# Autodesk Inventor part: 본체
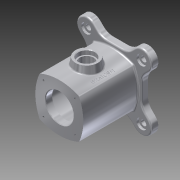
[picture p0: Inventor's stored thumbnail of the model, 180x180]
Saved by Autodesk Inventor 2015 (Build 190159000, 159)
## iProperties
Created: 2016-05
Part Number: 본체
Material: 알루미늄 6061
Document SubType Name: Modeling
Designer: Administrator
Density: 2.7 g/cm^3
Appearance: 알루미늄 - 평지
Mass: 1104.93 g
Surface Area: 865.283 cm^2
Volume: 409.235 cm^3
Author: Administrator
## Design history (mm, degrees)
sketch "스케치1" dims "d0" = 70
  geometry: L1 (49, 49)-(-49, 49); L2 (-49, 49)-(-49, -49); L3 (-49, -49)-(49, -49); L4 (49, -49)-(49, 49); L5 (49, 49)-(-49, -49); L6 (-49, 49)-(49, -49); L7 (0, -70)-(0, 70); L8 (-70, 0)-(70, 0); L9 (0, 0)-(-60.519, 60.519); L10 (0, 0)-(85.587, 0); L11 (-49, 23.544)-(-62.225, 36.77); L12 (-23.544, 49)-(-36.77, 62.225); L13 (-49, -23.544)-(-62.225, -36.77); L14 (-23.544, -49)-(-36.77, -62.225); L15 (49, 23.544)-(62.225, 36.77); L16 (23.544, 49)-(36.77, 62.225); L17 (23.544, -49)-(36.77, -62.225); L18 (49, -23.544)-(62.225, -36.77); L19 (23.544, 49)-(49, 49); L20 (49, 49)-(49, 23.544); L21 (49, -23.544)-(49, -49); L22 (23.544, -49)-(49, -49); L23 (-49, -23.544)-(-49, -49); L24 (-49, -49)-(-23.544, -49); A1 r 18 centre (-49.497, 49.497) between (-35.239, 60.483) and (-60.483, 35.239); A2 r 18 centre (-49.497, -49.497) between (-60.483, -35.239) and (-35.239, -60.483); A3 r 18 centre (49.497, 49.497) between (60.483, 35.239) and (35.239, 60.483); A4 r 18 centre (49.497, -49.497) between (35.239, -60.483) and (60.483, -35.239); 1 further point
  constraints: 48 end point, 21 symmetric about line, 16 point on circle, 5 collinear, 5 point on line, 4 centre point, 4 midpoint, 3 horizontal, 2 parallel, 1 coincident, 1 equal length, 1 perpendicular, 1 vertical, 12 other
  dimensions: "d1" = 98 distance of L3.end L2.end; "d2" = 98 distance of L2.end L1.end; "d4" = 135 deg angle of L10 L9; "d5" = 18 radius of A1; "d6" = 36 diameter of L11 L9; "d7" = 36 diameter of L12 L9
extrude "돌출1" new body sketch "스케치1" distance "d8" = 12; taper "d9" = 0 deg
fillet "모깎기1" dims "d10" = 25
sketch "스케치2"
  geometry: A1 r 18 centre (49.497, -49.497) between (36.77, -62.225) and (62.225, -36.77) reference; 2 further points
  constraints: 1 coincident
hole "구멍1" sketch "스케치2" at (49.497, -49.497) diameter "d11" = 10; stored, may be unused: countersink angle "d15" = 90 deg, drill point angle "d17" = 118 deg; dims "d12" = 6, "d13" = 18, "d14" = 4, "d16" = 15
sketch "스케치3"
  geometry: L1 (35.355, 35.355)-(-35.355, -35.355); L2 (0, 0)-(50, 0); L3 (35.355, -35.355)-(-35.355, 35.355); L4 (0, 0)-(50, 0); L5 (0, -43)-(0, 43); L6 (-43, 0)-(43, 0); C1 r 43 at (0, 0); A1 r 50 centre (0, 0) between (-35.355, -35.355) and (35.355, 35.355); A2 r 85.579 centre (0, 42.579) between (-35.355, -35.355) and (35.355, -35.355); A3 r 85.579 centre (42.579, 0) between (-35.355, 35.355) and (-35.355, -35.355); A4 r 85.579 centre (-42.579, 0) between (35.355, -35.355) and (35.355, 35.355); A5 r 85.579 centre (0, -42.579) between (35.355, 35.355) and (-35.355, 35.355); 1 further point
  constraints: 16 point on circle, 12 end point, 6 centre point, 2 coincident, 2 horizontal, 2 midpoint, 1 point on line
  dimensions: "d18" = 86 diameter of C1; "d20" = 100 diameter of A1; "d21" = 135 deg angle of L1 L2; "d22" = 135 deg angle of L4 L3; "d23" = 85.57874 radius of A2; "d24" = 85.57874 radius of A3; "d25" = 85.57874 radius of A4; "d73" = 86 distance of L6.end L6.start (derived); "d74" = 85.57874 radius of A5; "d75" = 86 distance of L5.start L5.end (derived)
extrude "돌출2" join sketch "스케치3" distance "d26" = 98; taper "d27" = 0 deg
fillet "모깎기2" dims "d28" = 3
fillet "모깎기3" dims "d29" = 3
fillet "모깎기4" dims "d30" = 3
node "작업 평면2"
sketch "스케치4"
  geometry: L1 (-64.497, 12)-(-38.891, 12) reference; C1 r 20 at (0, 61); 2 further points
  constraints: 1 centre point, 1 vertical alignment
  dimensions: "d32" = 40 diameter of C1; "d33" = 49 distance from line of L1 C1.centre
extrude "돌출3" join sketch "스케치4" distance "d34" = 30; taper "d35" = 10 deg
sketch "스케치5"
  geometry: C1 r 20 at (0, 0) reference; 2 further points
  constraints: 1 coincident
hole "구멍2" sketch "스케치5" at (0, 0) diameter "d36" = 25; stored, may be unused: countersink angle "d40" = 90 deg, drill point angle "d42" = 118 deg; dims "d37" = 6, "d38" = 30, "d39" = 8, "d41" = 30
sketch "스케치6"
  geometry: C1 r 25 at (0, 0); 1 further point
  constraints: 1 centre point, 1 coincident
  dimensions: "d43" = 50 diameter of C1
extrude "돌출4" cut sketch "스케치6" distance "d44" = 12; taper "d45" = 0 deg
sketch "스케치7"
  geometry: C1 r 25 at (0, 0) reference; C2 r 35 at (0, 0)
  constraints: 1 centre point, 1 coincident
  dimensions: "d46" = 70 diameter of C2
extrude "돌출5" cut sketch "스케치7" distance "d47" = 86; taper "d48" = 0 deg
sketch "스케치8"
  geometry: C1 r 25 at (0, 0); 1 further point
  constraints: 1 centre point, 1 coincident
  dimensions: "d49" = 50 diameter of C1
extrude "돌출6" cut sketch "스케치8" distance "d50" = 12; taper "d51" = 0 deg
fillet "모깎기5" dims "d52" = 3
chamfer "모따기1" distance "d53" = 1; stored, may be unused: second distance "d54" = 2, angle "d55" = 45 deg
sketch "스케치9" dims "d56" = 40
  geometry: L1 (0, 0)-(-28.284, -28.284); L2 (0, 0)-(40, 0); C1 r 26 at (0, 0) reference; 1 further point
  constraints: 4 end point, 2 coincident, 1 equal length, 1 horizontal, 3 other
  dimensions: "d57" = 135 deg angle of L1 L2
hole "구멍3" sketch "스케치9" at (-28.284, -28.284) diameter "d58" = 3.242; stored, may be unused: countersink angle "d62" = 90 deg, drill point angle "d64" = 118 deg; dims "d59" = 7, "d60" = 30, "d61" = 8, "d63" = 10
node "작업 평면3"
fillet "모깎기6" dims "d68" = 3
node "작업 평면4"
sketch "스케치10"
  geometry: L1 (34.285, 98)-(-34.285, 98) reference; L2 (0, -12)-(0, 98); 2 further points
  constraints: 2 coincident, 2 end point, 1 midpoint, 1 other
  dimensions: "d69" = 49 distance from line of L1 point (-29, 49); "d70" = 29 distance from line of L2 point (-29, 49)
feature "엠보싱1" sketch "스케치10" dims "d71" = 0.5, "d72" = 0
node "솔리드1"
mirror "대칭2"
mirror "대칭3"
pattern_circular "원형 패턴1" dims angle "d66" = 360 deg
mirror "대칭4"
other parameters: "d31" = -55
